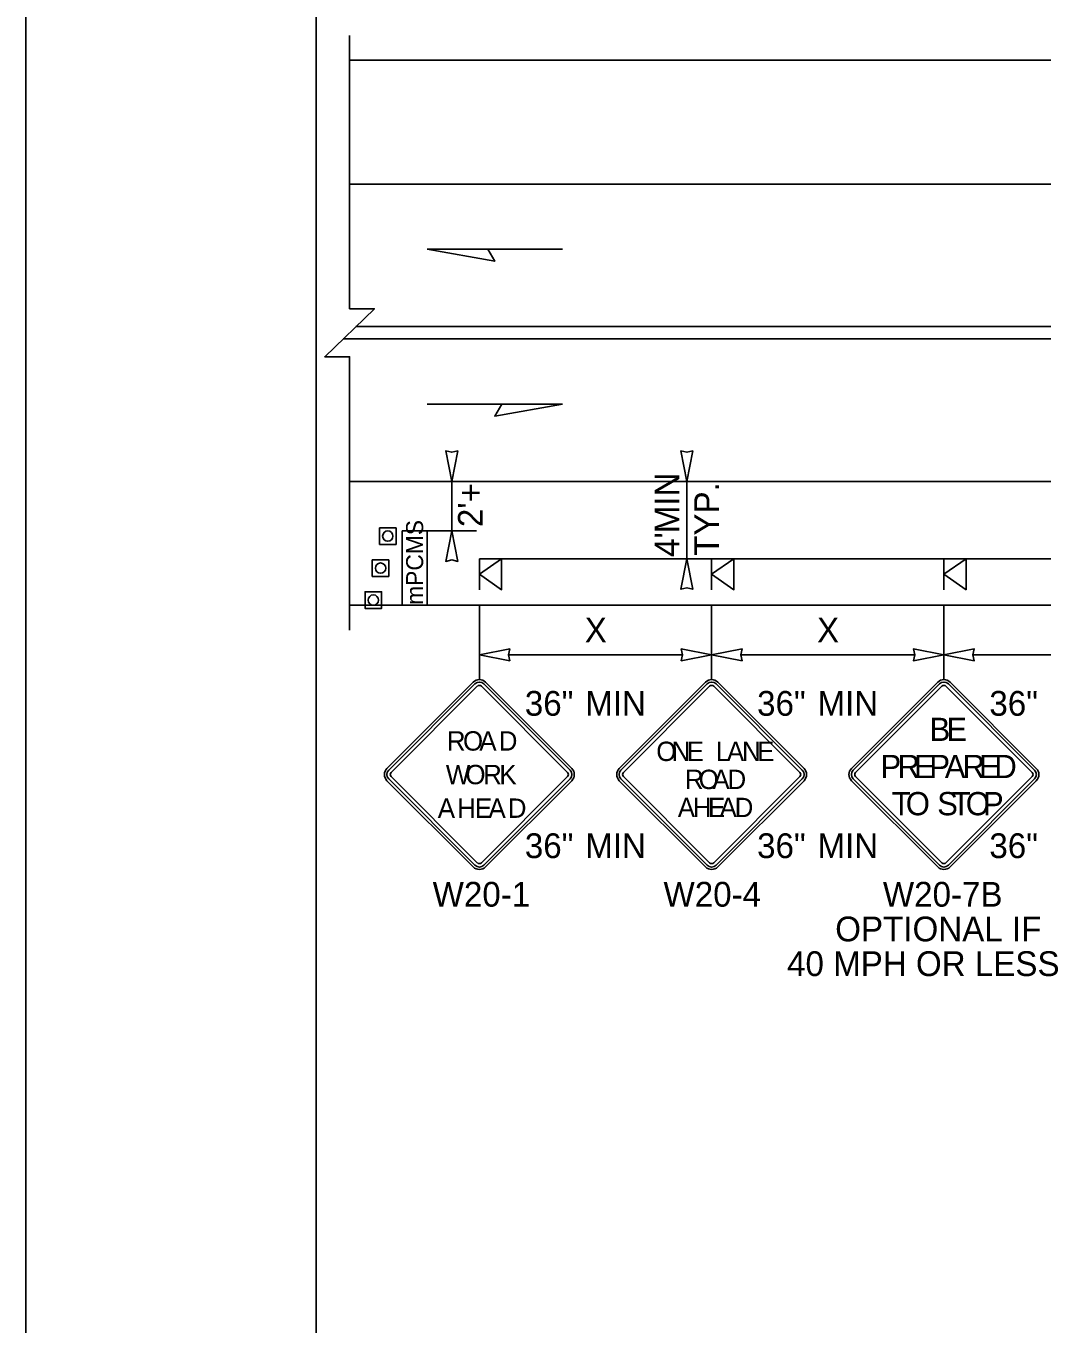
# Model space of a CAD drawing. Extents: x 99999.1 to 100095.7, y 99995 to 100010.7.
# Drawn here: x 100039.062 to 100042.344, y 100003.412 to 100007.603 of the extents above; entities that cross this region are included whole.
import ezdxf

# ---------------------------------------------------------------- set-up
doc = ezdxf.new("R2010")
doc.units = 0
for name, color, linetype in [('RD_ED_ShoulderPavedEdge', 7, 'Continuous'), ('RD_MK_LineDblYellowCenter', 7, 'Continuous'), ('RD_MK_LineEdgeWhite', 7, 'Continuous'), ('SH_GI_PlotLimits', 7, 'Continuous'), ('SH_GI_SheetBorder', 7, 'Continuous'), ('TR_SN_ConstructionSigns', 7, 'Continuous'), ('TR_WZ_PCMS', 7, 'Continuous'), ('TR_WZ_PortableSignMountBlk-Org', 7, 'Continuous'), ('TR_WZ_TrafficCone', 7, 'Continuous'), ('TR_WZ_WorkZoneDetails', 7, 'Continuous'), ('TR_WZ_WorkZoneTextCurrent', 7, 'Continuous')]:
    doc.layers.add(name, color=color, linetype=linetype)

msp = doc.modelspace()

# ---------------------------------------------------------------- linework, layer by layer
at = {"layer": 'RD_ED_ShoulderPavedEdge'}
for p, q in [((100040.1076, 100007.4923), (100055.6424, 100007.4923)), ((100040.1076, 100005.7323), (100055.6424, 100005.7323))]:
    msp.add_line(p, q, dxfattribs=at)
at = {"layer": 'RD_MK_LineDblYellowCenter'}
for p, q in [((100040.1282, 100006.6323), (100043.4767, 100006.6323)), ((100040.0869, 100006.5923), (100043.4767, 100006.5923))]:
    msp.add_line(p, q, dxfattribs=at)
at = {"layer": 'RD_MK_LineEdgeWhite'}
for p, q in [((100040.1076, 100007.0923), (100055.6424, 100007.0923)), ((100040.1076, 100006.1323), (100055.6424, 100006.1323))]:
    msp.add_line(p, q, dxfattribs=at)
at = {"layer": 'SH_GI_PlotLimits'}
msp.add_lwpolyline([(100039.0625, 99999.6875), (100056.0625, 99999.6875), (100056.0625, 100010.6875), (100039.0625, 100010.6875)], close=True, dxfattribs=at)
at = {"layer": 'SH_GI_SheetBorder'}
msp.add_line((100040, 100010.375), (100040, 100000), dxfattribs=at)
at = {"layer": 'TR_SN_ConstructionSigns'}
for p, q in [((100040.5068, 100005.4841), (100040.2283, 100005.2057)), ((100040.5123, 100005.4786), (100040.2339, 100005.2001)), ((100040.2416, 100005.1924), (100040.52, 100005.4708)), ((100040.5333, 100005.4708), (100040.8117, 100005.1924)), ((100040.8194, 100005.2001), (100040.541, 100005.4786)), ((100040.825, 100005.2057), (100040.5465, 100005.4841)), ((100041.2568, 100005.4841), (100040.9783, 100005.2057)), ((100041.2623, 100005.4786), (100040.9839, 100005.2001)), ((100040.9916, 100005.1924), (100041.27, 100005.4708)), ((100041.2833, 100005.4708), (100041.5617, 100005.1924)), ((100041.5694, 100005.2001), (100041.291, 100005.4786)), ((100041.575, 100005.2057), (100041.2965, 100005.4841)), ((100042.0068, 100005.4841), (100041.7283, 100005.2057)), ((100042.0123, 100005.4786), (100041.7339, 100005.2001)), ((100041.7416, 100005.1924), (100042.02, 100005.4708)), ((100042.0333, 100005.4708), (100042.3117, 100005.1924)), ((100042.3194, 100005.2001), (100042.041, 100005.4786)), ((100042.325, 100005.2057), (100042.0465, 100005.4841)), ((100040.2283, 100005.1659), (100040.5068, 100004.8875)), ((100040.2339, 100005.1714), (100040.5123, 100004.893)), ((100040.52, 100004.9007), (100040.2416, 100005.1792)), ((100040.8117, 100005.1792), (100040.5333, 100004.9007)), ((100040.541, 100004.893), (100040.8194, 100005.1714)), ((100040.5465, 100004.8875), (100040.825, 100005.1659)), ((100040.9783, 100005.1659), (100041.2568, 100004.8875)), ((100040.9839, 100005.1714), (100041.2623, 100004.893)), ((100041.27, 100004.9007), (100040.9916, 100005.1792)), ((100041.5617, 100005.1792), (100041.2833, 100004.9007)), ((100041.291, 100004.893), (100041.5694, 100005.1714)), ((100041.2965, 100004.8875), (100041.575, 100005.1659)), ((100041.7283, 100005.1659), (100042.0068, 100004.8875)), ((100041.7339, 100005.1714), (100042.0123, 100004.893)), ((100042.02, 100004.9007), (100041.7416, 100005.1792)), ((100042.3117, 100005.1792), (100042.0333, 100004.9007)), ((100042.041, 100004.893), (100042.3194, 100005.1714)), ((100042.0465, 100004.8875), (100042.325, 100005.1659))]:
    msp.add_line(p, q, dxfattribs=at)
for centre, radius, start, end in [((100040.5267, 100005.4642), 0.0281, 45, 135), ((100041.2767, 100005.4642), 0.0281, 45, 135), ((100042.0267, 100005.4642), 0.0281, 45, 135), ((100040.5267, 100005.4642), 0.0203, 45, 135), ((100040.5267, 100005.4642), 0.00937, 45, 135), ((100041.2767, 100005.4642), 0.0203, 45, 135), ((100041.2767, 100005.4642), 0.00937, 45, 135), ((100042.0267, 100005.4642), 0.0203, 45, 135), ((100042.0267, 100005.4642), 0.00937, 45, 135), ((100040.2482, 100005.1858), 0.0281, 135, 225), ((100040.2482, 100005.1858), 0.0203, 135, 225), ((100040.2482, 100005.1858), 0.00937, 135, 225), ((100040.8051, 100005.1858), 0.00937, 315, 45), ((100040.8051, 100005.1858), 0.0203, 315, 45), ((100040.8051, 100005.1858), 0.0281, 315, 45), ((100040.9982, 100005.1858), 0.0281, 135, 225), ((100040.9982, 100005.1858), 0.0203, 135, 225), ((100040.9982, 100005.1858), 0.00937, 135, 225), ((100041.5551, 100005.1858), 0.00937, 315, 45), ((100041.5551, 100005.1858), 0.0203, 315, 45), ((100041.5551, 100005.1858), 0.0281, 315, 45), ((100041.7482, 100005.1858), 0.0281, 135, 225), ((100041.7482, 100005.1858), 0.0203, 135, 225), ((100041.7482, 100005.1858), 0.00937, 135, 225), ((100042.3051, 100005.1858), 0.00937, 315, 45), ((100042.3051, 100005.1858), 0.0203, 315, 45), ((100042.3051, 100005.1858), 0.0281, 315, 45), ((100040.5267, 100004.9074), 0.00937, 225, 315), ((100041.2767, 100004.9074), 0.00937, 225, 315), ((100042.0267, 100004.9074), 0.00937, 225, 315), ((100040.5267, 100004.9074), 0.0281, 225, 315), ((100040.5267, 100004.9074), 0.0203, 225, 315), ((100041.2767, 100004.9074), 0.0281, 225, 315), ((100041.2767, 100004.9074), 0.0203, 225, 315), ((100042.0267, 100004.9074), 0.0281, 225, 315), ((100042.0267, 100004.9074), 0.0203, 225, 315)]:
    msp.add_arc(centre, radius, start, end, dxfattribs=at)
at = {"layer": 'TR_WZ_PCMS'}
msp.add_lwpolyline([(100040.3576, 100005.7323), (100040.3576, 100005.9723), (100040.2776, 100005.9723), (100040.2776, 100005.7323)], close=True, dxfattribs=at)
msp.add_lwpolyline([(100040.3576, 100005.7323), (100040.3576, 100005.9723), (100040.2776, 100005.9723), (100040.2776, 100005.7323), (100040.3576, 100005.7323)], dxfattribs=at)
at = {"layer": 'TR_WZ_PortableSignMountBlk-Org'}
for p, q in [((100040.5267, 100005.7824), (100040.5267, 100005.8824)), ((100041.2767, 100005.7824), (100041.2767, 100005.8824)), ((100042.0267, 100005.7824), (100042.0267, 100005.8824))]:
    msp.add_line(p, q, dxfattribs=at)
for points in [[(100040.5267, 100005.8323), (100040.5985, 100005.8824), (100040.5985, 100005.7824)], [(100041.2767, 100005.8323), (100041.3485, 100005.8824), (100041.3485, 100005.7824)], [(100042.0267, 100005.8323), (100042.0985, 100005.8824), (100042.0985, 100005.7824)]]:
    msp.add_lwpolyline(points, close=True, dxfattribs=at)
at = {"layer": 'TR_WZ_TrafficCone'}
for points in [[(100040.2042, 100005.9823), (100040.2576, 100005.9823), (100040.2576, 100005.929), (100040.2042, 100005.929), (100040.2042, 100005.9823)], [(100040.2042, 100005.929), (100040.2576, 100005.929), (100040.2576, 100005.9823), (100040.2042, 100005.9823), (100040.2042, 100005.929)], [(100040.1809, 100005.879), (100040.2342, 100005.879), (100040.2342, 100005.8257), (100040.1809, 100005.8257), (100040.1809, 100005.879)], [(100040.1809, 100005.8257), (100040.2342, 100005.8257), (100040.2342, 100005.879), (100040.1809, 100005.879), (100040.1809, 100005.8257)], [(100040.1576, 100005.7757), (100040.2109, 100005.7757), (100040.2109, 100005.7223), (100040.1576, 100005.7223), (100040.1576, 100005.7757)], [(100040.1576, 100005.7223), (100040.2109, 100005.7223), (100040.2109, 100005.7757), (100040.1576, 100005.7757), (100040.1576, 100005.7223)]]:
    msp.add_lwpolyline(points, dxfattribs=at)
for centre in [(100040.2309, 100005.9557), (100040.2076, 100005.8523), (100040.1842, 100005.749)]:
    msp.add_circle(centre, 0.0167, dxfattribs=at)
at = {"layer": 'TR_WZ_WorkZoneDetails'}
for p, q in [((100040.5541, 100006.8816), (100040.7952, 100006.8816)), ((100040.5987, 100006.3816), (100040.3576, 100006.3816)), ((100040.3576, 100006.1323), (100040.5176, 100006.1323)), ((100040.4376, 100006.1323), (100040.4376, 100005.9723)), ((100041.1167, 100006.1323), (100041.2767, 100006.1323)), ((100041.1967, 100005.8824), (100041.1967, 100006.1323)), ((100040.3576, 100005.9723), (100040.5176, 100005.9723)), ((100040.5267, 100005.8824), (100043.5267, 100005.8824)), ((100041.1167, 100005.8824), (100041.2767, 100005.8824)), ((100040.5267, 100005.7326), (100040.5267, 100005.4923)), ((100041.2767, 100005.7323), (100041.2767, 100005.4923)), ((100042.0267, 100005.7323), (100042.0267, 100005.4923)), ((100041.1829, 100005.5723), (100040.6204, 100005.5723)), ((100041.9329, 100005.5723), (100041.3704, 100005.5723)), ((100042.6829, 100005.5723), (100042.1204, 100005.5723))]:
    msp.add_line(p, q, dxfattribs=at)
msp.add_lwpolyline([(100040.1076, 100005.6523), (100040.1076, 100006.5349), (100040.0275, 100006.5349), (100040.1876, 100006.6898), (100040.1076, 100006.6898), (100040.1076, 100007.5723)], dxfattribs=at)
for points in [[(100040.3576, 100006.8816), (100040.5764, 100006.843), (100040.5541, 100006.8816)], [(100040.7952, 100006.3816), (100040.5764, 100006.343), (100040.5987, 100006.3816)], [(100040.4376, 100006.1323), (100040.4183, 100006.2306), (100040.4376, 100006.2261), (100040.4568, 100006.2306)], [(100041.1967, 100006.1323), (100041.1774, 100006.2306), (100041.1967, 100006.2261), (100041.2159, 100006.2306)], [(100040.4376, 100005.9723), (100040.4183, 100005.8741), (100040.4376, 100005.8786), (100040.4568, 100005.8741)], [(100041.1967, 100005.8824), (100041.1774, 100005.7841), (100041.1967, 100005.7887), (100041.2159, 100005.7841)], [(100040.5267, 100005.5723), (100040.6249, 100005.5916), (100040.6204, 100005.5723), (100040.6249, 100005.5531)], [(100041.2767, 100005.5723), (100041.1784, 100005.5916), (100041.1829, 100005.5723), (100041.1784, 100005.5531)], [(100041.2767, 100005.5723), (100041.3749, 100005.5916), (100041.3704, 100005.5723), (100041.3749, 100005.5531)], [(100042.0267, 100005.5723), (100041.9284, 100005.5916), (100041.9329, 100005.5723), (100041.9284, 100005.5531)], [(100042.0267, 100005.5723), (100042.1249, 100005.5916), (100042.1204, 100005.5723), (100042.1249, 100005.5531)]]:
    msp.add_lwpolyline(points, close=True, dxfattribs=at)

# ---------------------------------------------------------------- texts
at = {"layer": 'TR_SN_ConstructionSigns'}
for s, p in [('36"', (100040.6734, 100005.3756)), ('MIN', (100040.8684, 100005.3756)), ('36"', (100041.4234, 100005.3756)), ('MIN', (100041.6184, 100005.3756)), ('36"', (100042.1734, 100005.3756)), ('36"', (100040.6734, 100004.916)), ('MIN', (100040.8684, 100004.916)), ('36"', (100041.4234, 100004.916)), ('MIN', (100041.6184, 100004.916)), ('36"', (100042.1734, 100004.916)), ('W20-1', (100040.3757, 100004.7592)), ('W20-4', (100041.1212, 100004.7592)), ('W20-7B', (100041.8296, 100004.7592)), ('OPTIONAL IF', (100041.6757, 100004.6472)), ('40 MPH OR LESS', (100041.5202, 100004.5352))]:
    msp.add_text(s, height=0.08, rotation=360, dxfattribs=at).set_placement(p)
for s, height, p in [('B', 0.075, (100041.9804, 100005.2943)), ('E', 0.075, (100042.0347, 100005.2943)), ('R', 0.0625, (100040.4216, 100005.2631)), ('O', 0.0625, (100040.4737, 100005.2631)), ('A', 0.0625, (100040.5265, 100005.2631)), ('D', 0.0625, (100040.5892, 100005.2631)), ('O', 0.0625, (100041.0979, 100005.2295)), ('N', 0.0625, (100041.1473, 100005.2295)), ('E', 0.0625, (100041.196, 100005.2295)), ('L', 0.0625, (100041.2904, 100005.2295)), ('A', 0.0625, (100041.326, 100005.2295)), ('N', 0.0625, (100041.3748, 100005.2295)), ('E', 0.0625, (100041.4235, 100005.2295)), ('P', 0.075, (100041.8218, 100005.1743)), ('R', 0.075, (100041.877, 100005.1743)), ('E', 0.075, (100041.9302, 100005.1743)), ('P', 0.075, (100041.9797, 100005.1743)), ('A', 0.075, (100042.0296, 100005.1743)), ('R', 0.075, (100042.0868, 100005.1743)), ('E', 0.075, (100042.1401, 100005.1743)), ('D', 0.075, (100042.1896, 100005.1743)), ('W', 0.0625, (100040.4183, 100005.1545)), ('O', 0.0625, (100040.4816, 100005.1545)), ('R', 0.0625, (100040.5388, 100005.1545)), ('K', 0.0625, (100040.5912, 100005.1545)), ('R', 0.0625, (100041.1904, 100005.1389)), ('O', 0.0625, (100041.2348, 100005.1389)), ('A', 0.0625, (100041.2792, 100005.1389)), ('D', 0.0625, (100041.3279, 100005.1389)), ('A', 0.0625, (100040.3923, 100005.046)), ('H', 0.0625, (100040.4548, 100005.046)), ('E', 0.0625, (100040.5123, 100005.046)), ('A', 0.0625, (100040.556, 100005.046)), ('D', 0.0625, (100040.6185, 100005.046)), ('A', 0.0625, (100041.1673, 100005.0483)), ('H', 0.0625, (100041.216, 100005.0483)), ('E', 0.0625, (100041.2648, 100005.0483)), ('A', 0.0625, (100041.3023, 100005.0483)), ('D', 0.0625, (100041.351, 100005.0483)), ('T', 0.075, (100041.8584, 100005.0543)), ('O', 0.075, (100041.9035, 100005.0543)), ('S', 0.075, (100042.005, 100005.0543)), ('T', 0.075, (100042.0521, 100005.0543)), ('O', 0.075, (100042.0972, 100005.0543)), ('P', 0.075, (100042.1529, 100005.0543))]:
    msp.add_text(s, height=height, dxfattribs=at).set_placement(p)
at = {"layer": 'TR_WZ_PCMS'}
msp.add_text('mPCMS', height=0.055, rotation=90, dxfattribs=at).set_placement((100040.3451, 100005.7338))
at = {"layer": 'TR_WZ_WorkZoneTextCurrent'}
for s, rotation, p in [("2'+", 90, (100040.5376, 100005.9846)), ('MIN', 90, (100041.1727, 100005.9648)), ('TYP.', 90, (100041.3007, 100005.892)), ("4'", 90, (100041.1727, 100005.8883)), ('X', 360, (100040.8669, 100005.6123)), ('X', 360, (100041.6169, 100005.6123))]:
    msp.add_text(s, height=0.08, rotation=rotation, dxfattribs=at).set_placement(p)

doc.saveas('drawing.dxf')
